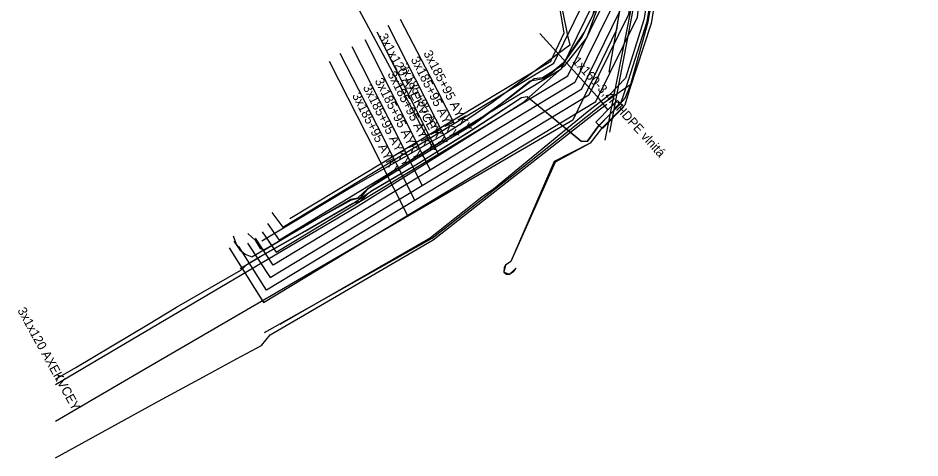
# Model space of a CAD drawing. Extents: x -746464 to -745690, y -1051581 to -1049993.
# Drawn here: x -746462.2 to -746363.4, y -1051115.9 to -1051067.7 of the extents above; entities that cross this region are included whole.
import ezdxf

# ---------------------------------------------------------------- set-up
doc = ezdxf.new("R2010")
doc.units = 0
for name, color, linetype in [('04_CETIN_NN', 7, 'Continuous'), ('04_CETIN_sdelovaci_podzem', 7, 'Continuous'), ('51_PVaK_kanal_destova_overena poloha', 7, 'Continuous'), ('51_PVaK_vodovod_overena poloha_rad', 7, 'Continuous'), ('51_PVaK_vodovod_zruseno_overena poloha', 7, 'Continuous'), ('55_PREdi_chranicky', 7, 'Continuous'), ('55_PREdi_NN', 7, 'Continuous'), ('55_PREdi_NN_popisy', 7, 'Continuous'), ('55_PREdi_stavby_popisy', 7, 'Continuous'), ('55_PREdi_VN', 7, 'Continuous'), ('55_PREdi_VN_popisy', 7, 'Continuous'), ('55_PREdi_ZRUSENE_elektro', 7, 'Continuous')]:
    doc.layers.add(name, color=color, linetype=linetype)

msp = doc.modelspace()

# ---------------------------------------------------------------- linework, layer by layer
at = {"layer": '04_CETIN_NN'}
msp.add_lwpolyline([(-746458.107, -1051107.826), (-746424.97, -1051088.25), (-746406.84, -1051076.89), (-746402.31, -1051072.9), (-746399.92, -1051069.86), (-746397.76, -1051063.82), (-746397.02, -1051057.34)], dxfattribs=at)
at = {"layer": '04_CETIN_sdelovaci_podzem'}
msp.add_lwpolyline([(-746458.107, -1051107.826), (-746424.97, -1051088.25), (-746406.84, -1051076.89), (-746402.31, -1051072.9), (-746399.92, -1051069.86), (-746397.76, -1051063.82), (-746397.02, -1051057.34)], dxfattribs=at)
at = {"layer": '51_PVaK_kanal_destova_overena poloha'}
msp.add_line((-746397.48, -1051073.6), (-746391.17, -1051037.62), dxfattribs=at)
at = {"layer": '51_PVaK_vodovod_overena poloha_rad'}
msp.add_line((-746389.95, -1051040.83), (-746397.441, -1051080.195), dxfattribs=at)
msp.add_lwpolyline([(-746393.58, -1051037.65), (-746392.47, -1051039.51), (-746396.65, -1051068.98), (-746401.46, -1051078.87), (-746427.34, -1051093.95), (-746448.61, -1051106.33), (-746458.107, -1051111.861)], dxfattribs=at)
at = {"layer": '51_PVaK_vodovod_zruseno_overena poloha'}
msp.add_line((-746390.02, -1051041.23), (-746397.95, -1051081.06), dxfattribs=at)
at = {"layer": '55_PREdi_chranicky'}
msp.add_lwpolyline([(-746396.995, -1051077.137), (-746396.567, -1051076.7), (-746396.21, -1051077.05), (-746395.853, -1051077.4), (-746398.203, -1051079.8), (-746398.56, -1051079.45), (-746398.917, -1051079.1), (-746397.228, -1051077.375), (-746396.995, -1051077.137)], close=True, dxfattribs=at)
at = {"layer": '55_PREdi_NN'}
for points in [[(-746396.33, -1051057.725), (-746397.29, -1051066.741), (-746401.237, -1051074.729), (-746434.263, -1051094.758), (-746436.212, -1051091.799)], [(-746435.468, -1051091.087), (-746433.94, -1051093.306), (-746402.004, -1051074.024), (-746398.266, -1051066.458), (-746397.336, -1051057.726)], [(-746398.332, -1051057.639), (-746399.241, -1051066.175), (-746402.772, -1051073.32), (-746433.567, -1051091.994), (-746434.86, -1051090.188)], [(-746434.411, -1051088.984), (-746433.216, -1051090.589), (-746403.539, -1051072.615), (-746400.217, -1051065.892), (-746399.333, -1051057.595)], [(-746394.505, -1051059.699), (-746395.339, -1051067.307), (-746399.702, -1051076.138), (-746435.004, -1051097.485), (-746438.028, -1051092.693)], [(-746437.09, -1051092.346), (-746434.604, -1051096.098), (-746400.47, -1051075.434), (-746396.314, -1051067.024), (-746395.568, -1051059.651)], [(-746437.03, -1051091.26), (-746436.24, -1051092.01), (-746435.71, -1051092.92), (-746435.23, -1051093.06), (-746430.15, -1051090.05), (-746425.69, -1051087.58), (-746424.67, -1051087.34), (-746423.82, -1051086.31), (-746420.99, -1051084.34), (-746416.69, -1051081.69), (-746412.49, -1051079.32), (-746408.27, -1051076.31), (-746405.68, -1051074.32), (-746404.77, -1051074.21), (-746402.63, -1051072.85), (-746400.19, -1051069.27), (-746399, -1051066.85), (-746398.46, -1051063.94), (-746398.07, -1051059.17)], [(-746439.108, -1051092.85), (-746435.332, -1051098.842), (-746398.935, -1051076.843), (-746394.363, -1051067.59), (-746393.511, -1051059.809)]]:
    msp.add_lwpolyline(points, dxfattribs=at)
at = {"layer": '55_PREdi_NN_popisy'}
for points in [[(-746421.693, -1051068.466), (-746417.641, -1051076.431), (-746415.374, -1051080.962)], [(-746420.346, -1051067.799), (-746416.231, -1051075.731), (-746414.457, -1051079.227)], [(-746422.911, -1051069.186), (-746418.886, -1051077.165), (-746416.188, -1051082.588)], [(-746424.232, -1051070.043), (-746420.215, -1051078.025), (-746417.078, -1051084.336)], [(-746426.954, -1051071.526), (-746422.883, -1051079.481), (-746418.74, -1051087.65)], [(-746425.641, -1051070.793), (-746421.598, -1051078.762), (-746417.955, -1051086.019)], [(-746428.14, -1051072.417), (-746424.07, -1051080.373), (-746419.542, -1051089.298)]]:
    msp.add_lwpolyline(points, dxfattribs=at)
at = {"layer": '55_PREdi_stavby_popisy'}
msp.add_lwpolyline([(-746405.043, -1051069.381), (-746398.805, -1051076.229), (-746397.608, -1051077.763)], dxfattribs=at)
at = {"layer": '55_PREdi_VN'}
for points in [[(-746395.917, -1051076.277), (-746395.389, -1051074.598), (-746393.294, -1051068.057), (-746391.518, -1051057.571), (-746390.759, -1051055.966), (-746388.906, -1051050.796)], [(-746395.1, -1051074.94), (-746393.182, -1051068.096), (-746391.086, -1051056.19)], [(-746438.65, -1051091.538), (-746438.331, -1051092.437), (-746437.93, -1051093.072), (-746437.35, -1051093.54), (-746436.6, -1051093.82), (-746429.54, -1051089.7), (-746425.76, -1051087.51), (-746424.99, -1051087.37), (-746423.97, -1051086.44), (-746419.31, -1051083.5), (-746412.27, -1051079.28), (-746409.84, -1051077.48), (-746406.13, -1051074.57), (-746404.61, -1051074.32), (-746402.29, -1051072.4), (-746400.46, -1051069.83), (-746399.21, -1051067.3), (-746398.46, -1051064.03), (-746397.991, -1051058.487), (-746397.91, -1051057.988)], [(-746438.57, -1051092.122), (-746437.93, -1051093.072), (-746437.35, -1051093.54), (-746436.6, -1051093.82), (-746429.54, -1051089.7), (-746425.76, -1051087.51), (-746424.99, -1051087.37), (-746423.97, -1051086.44), (-746419.31, -1051083.5), (-746412.27, -1051079.28), (-746409.84, -1051077.48), (-746406.13, -1051074.57), (-746404.61, -1051074.32), (-746403.67, -1051073.61), (-746402.29, -1051072.4), (-746400.46, -1051069.83), (-746399.21, -1051067.3), (-746398.46, -1051064.03), (-746397.82, -1051058.01)], [(-746437.88, -1051095.12), (-746435.66, -1051093.792), (-746430.78, -1051091.032), (-746425.26, -1051087.812), (-746423.53, -1051086.632), (-746418.63, -1051083.742), (-746412.79, -1051080.142), (-746409.03, -1051077.702), (-746407.05, -1051076.402), (-746406.43, -1051076.282), (-746400.5, -1051081.16), (-746399.81, -1051081.17), (-746398.56, -1051079.45), (-746396.21, -1051077.05), (-746395.71, -1051076.46), (-746395.1, -1051074.94)], [(-746458.107, -1051107.214), (-746455.898, -1051105.933), (-746450.016, -1051102.462), (-746447.945, -1051101.211), (-746444.877, -1051099.352), (-746437.809, -1051095.293), (-746437.061, -1051094.613), (-746435.689, -1051093.792), (-746430.809, -1051091.032), (-746425.553, -1051087.954), (-746424.724, -1051087.727), (-746423.559, -1051086.632), (-746418.659, -1051083.742), (-746412.819, -1051080.142), (-746409.059, -1051077.702), (-746407.079, -1051076.402), (-746406.459, -1051076.282), (-746400.529, -1051081.16), (-746399.839, -1051081.17), (-746398.589, -1051079.45), (-746396.239, -1051077.082), (-746395.917, -1051076.277)]]:
    msp.add_lwpolyline(points, dxfattribs=at)
at = {"layer": '55_PREdi_VN_popisy'}
msp.add_lwpolyline([(-746425.928, -1051064.82), (-746420.438, -1051075.038), (-746416.847, -1051081.795)], dxfattribs=at)
at = {"layer": '55_PREdi_ZRUSENE_elektro'}
for points in [[(-746278.152, -1051020.538), (-746272.98, -1051020.897), (-746273.167, -1051027.65), (-746328.844, -1051024.925), (-746329.266, -1051031.449), (-746350.812, -1051031.118), (-746366.671, -1051031.76), (-746384.934, -1051031.584), (-746388, -1051045.043), (-746389.672, -1051050.564), (-746391.617, -1051056.146), (-746391.114, -1051057.599), (-746392.877, -1051068.295), (-746395.244, -1051075.498)], [(-746391.9, -1051057.441), (-746393.651, -1051067.878), (-746395.673, -1051074.283), (-746397.412, -1051076.085), (-746399.861, -1051078.007), (-746410.146, -1051086.422), (-746410.808, -1051086.873)], [(-746402.583, -1051058.283), (-746403.959, -1051060.047), (-746402.02, -1051069.587), (-746401.772, -1051070.656), (-746402.304, -1051071.052), (-746410.212, -1051076.892), (-746413.86, -1051079.365), (-746415.272, -1051080.307), (-746425.734, -1051086.236), (-746435.5, -1051092.122)], [(-746432.45, -1051089.647), (-746403.868, -1051072.392), (-746402.378, -1051069.308), (-746403.959, -1051060.047)], [(-746395.244, -1051075.498), (-746395.738, -1051077.217), (-746398.294, -1051079.773), (-746399.54, -1051081.405), (-746403.363, -1051083.466), (-746408.23, -1051094.338), (-746408.809, -1051094.75), (-746408.963, -1051094.992), (-746409.015, -1051095.499), (-746408.697, -1051095.741), (-746408.398, -1051095.724), (-746407.912, -1051095.387), (-746407.646, -1051095.07)], [(-746395.244, -1051075.498), (-746395.738, -1051077.217), (-746398.294, -1051079.773), (-746399.54, -1051081.405), (-746403.48, -1051083.384), (-746408.23, -1051094.338), (-746408.809, -1051094.75), (-746409.015, -1051095.499), (-746408.398, -1051095.724), (-746407.646, -1051095.07)], [(-746397.885, -1051076.845), (-746395.1, -1051074.94)], [(-746458.107, -1051115.851), (-746446.833, -1051109.638), (-746441.921, -1051106.955), (-746438.292, -1051105.005), (-746435.54, -1051103.527), (-746434.598, -1051102.358), (-746416.758, -1051091.963), (-746399.183, -1051078.196), (-746398.266, -1051077.523), (-746397.731, -1051077.131)], [(-746435.21, -1051102.13), (-746416.863, -1051091.789), (-746408.114, -1051084.949), (-746397.885, -1051076.845)], [(-746410.808, -1051086.873), (-746411.427, -1051087.289), (-746417.045, -1051091.743), (-746433.526, -1051101.256)]]:
    msp.add_lwpolyline(points, dxfattribs=at)

# ---------------------------------------------------------------- texts
at = {"layer": '55_PREdi_NN_popisy'}
for rotation, p in [(297.41813, (-746417.845, -1051071.535)), (296.96763, (-746419.221, -1051072.222)), (296.71253, (-746421.777, -1051073.809)), (296.77355, (-746420.452, -1051072.95)), (296.90158, (-746423.174, -1051074.552)), (297.10598, (-746424.474, -1051075.276)), (297.09662, (-746425.66, -1051076.167))]:
    msp.add_text('3x185+95 AYKY', height=1, rotation=rotation, dxfattribs=at).set_placement(p)
at = {"layer": '55_PREdi_stavby_popisy'}
msp.add_text('1x160-3,4mHDPE vlnitá', height=1, rotation=312.32679, dxfattribs=at).set_placement((-746401.554, -1051072.468))
at = {"layer": '55_PREdi_VN_popisy'}
for rotation, p in [(298.24771, (-746422.743, -1051069.692)), (298.8409, (-746462.323, -1051099.693))]:
    msp.add_text('3x1x120 AXEKVCEY', height=1, rotation=rotation, dxfattribs=at).set_placement(p)

doc.saveas('drawing.dxf')
